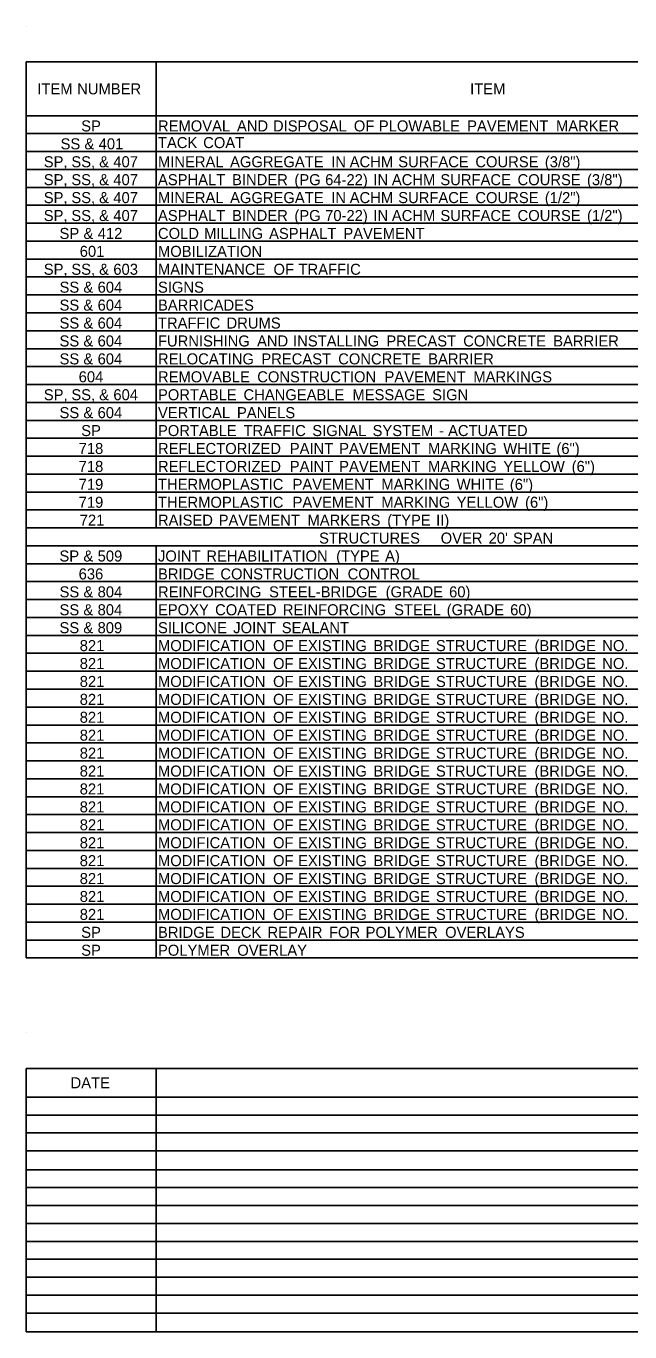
# Model space of a CAD drawing. Extents: x 544420 to 1930787, y -1947044 to 596640.
# Drawn here: x 552193 to 552521, y -1946914 to -1946204 of the extents above; entities that cross this region are included whole.
import ezdxf

# ---------------------------------------------------------------- set-up
doc = ezdxf.new("R2010")
doc.units = 0
doc.layers.add('Default', color=7, linetype='Continuous')

msp = doc.modelspace()

# ---------------------------------------------------------------- linework, layer by layer
at = {"layer": 'Default'}
for p, q in [((552192.61, -1946203.74), (552192.61, -1946203.74)), ((552192.61, -1946223.24), (552943.36, -1946223.24)), ((552192.61, -1946710.74), (552192.61, -1946223.24)), ((552263.3, -1946476.74), (552263.3, -1946223.24)), ((552192.61, -1946252.49), (552943.36, -1946252.49)), ((552192.61, -1946252.49), (552943.36, -1946252.49)), ((552263.3, -1946476.74), (552263.3, -1946252.49)), ((552192.61, -1946262.24), (552943.36, -1946262.24)), ((552192.61, -1946271.99), (552943.36, -1946271.99)), ((552192.61, -1946281.74), (552943.36, -1946281.74)), ((552192.61, -1946291.49), (552943.36, -1946291.49)), ((552192.61, -1946301.24), (552943.36, -1946301.24)), ((552192.61, -1946310.99), (552943.36, -1946310.99)), ((552192.61, -1946320.74), (552943.36, -1946320.74)), ((552192.61, -1946330.49), (552943.36, -1946330.49)), ((552192.61, -1946340.24), (552943.36, -1946340.24)), ((552192.61, -1946349.99), (552943.36, -1946349.99)), ((552192.61, -1946359.74), (552943.36, -1946359.74)), ((552192.61, -1946369.49), (552943.36, -1946369.49)), ((552192.61, -1946379.24), (552943.36, -1946379.24)), ((552192.61, -1946388.99), (552943.36, -1946388.99)), ((552192.61, -1946398.74), (552943.36, -1946398.74)), ((552192.61, -1946408.49), (552943.36, -1946408.49)), ((552192.61, -1946418.24), (552943.36, -1946418.24)), ((552192.61, -1946427.99), (552943.36, -1946427.99)), ((552192.61, -1946437.74), (552943.36, -1946437.74)), ((552192.61, -1946447.49), (552943.36, -1946447.49)), ((552192.61, -1946457.24), (552943.36, -1946457.24)), ((552192.61, -1946466.99), (552943.36, -1946466.99)), ((552192.61, -1946476.74), (552943.36, -1946476.74)), ((552192.61, -1946476.74), (552943.36, -1946476.74)), ((552192.61, -1946486.49), (552943.36, -1946486.49)), ((552192.61, -1946486.49), (552943.36, -1946486.49)), ((552263.3, -1946710.74), (552263.3, -1946486.49)), ((552263.3, -1946710.74), (552263.3, -1946486.49)), ((552192.61, -1946496.24), (552943.36, -1946496.24)), ((552192.61, -1946505.99), (552943.36, -1946505.99)), ((552192.61, -1946515.74), (552943.36, -1946515.74)), ((552192.61, -1946525.49), (552943.36, -1946525.49)), ((552192.61, -1946535.24), (552943.36, -1946535.24)), ((552192.61, -1946544.99), (552943.36, -1946544.99)), ((552263.3, -1946544.99), (552943.36, -1946544.99)), ((552192.61, -1946554.74), (552943.36, -1946554.74)), ((552263.3, -1946554.74), (552943.36, -1946554.74)), ((552192.61, -1946564.49), (552943.36, -1946564.49)), ((552263.3, -1946564.49), (552943.36, -1946564.49)), ((552192.61, -1946574.24), (552943.36, -1946574.24)), ((552263.3, -1946574.24), (552943.36, -1946574.24)), ((552192.61, -1946583.99), (552943.36, -1946583.99)), ((552263.3, -1946583.99), (552943.36, -1946583.99)), ((552192.61, -1946593.74), (552943.36, -1946593.74)), ((552263.3, -1946593.74), (552943.36, -1946593.74)), ((552192.61, -1946603.49), (552943.36, -1946603.49)), ((552263.3, -1946603.49), (552943.36, -1946603.49)), ((552192.61, -1946613.24), (552943.36, -1946613.24)), ((552263.3, -1946613.24), (552943.36, -1946613.24)), ((552192.61, -1946622.99), (552943.36, -1946622.99)), ((552263.3, -1946622.99), (552943.36, -1946622.99)), ((552192.61, -1946632.74), (552943.36, -1946632.74)), ((552263.3, -1946632.74), (552943.36, -1946632.74)), ((552192.61, -1946642.49), (552943.36, -1946642.49)), ((552263.3, -1946642.49), (552943.36, -1946642.49)), ((552192.61, -1946652.24), (552943.36, -1946652.24)), ((552263.3, -1946652.24), (552943.36, -1946652.24)), ((552192.61, -1946661.99), (552943.36, -1946661.99)), ((552263.3, -1946661.99), (552943.36, -1946661.99)), ((552192.61, -1946671.74), (552943.36, -1946671.74)), ((552263.3, -1946671.74), (552943.36, -1946671.74)), ((552192.61, -1946681.49), (552943.36, -1946681.49)), ((552263.3, -1946681.49), (552943.36, -1946681.49)), ((552192.61, -1946691.24), (552943.36, -1946691.24)), ((552263.3, -1946691.24), (552943.36, -1946691.24)), ((552192.61, -1946700.99), (552263.3, -1946700.99)), ((552192.61, -1946700.99), (552943.36, -1946700.99)), ((552192.61, -1946710.74), (552943.36, -1946710.74)), ((552192.61, -1946751.36), (552192.61, -1946751.36)), ((552192.61, -1946770.86), (552943.36, -1946770.86)), ((552192.61, -1946914.18), (552192.61, -1946770.86)), ((552263.3, -1946914.18), (552263.3, -1946770.86)), ((552192.61, -1946786.46), (552943.36, -1946786.46)), ((552192.61, -1946796.21), (552943.36, -1946796.21)), ((552192.61, -1946805.96), (552943.36, -1946805.96)), ((552192.61, -1946815.71), (552943.36, -1946815.71)), ((552192.61, -1946825.95), (552943.36, -1946825.95)), ((552192.61, -1946835.7), (552943.36, -1946835.7)), ((552192.61, -1946845.45), (552943.36, -1946845.45)), ((552192.61, -1946855.2), (552943.36, -1946855.2)), ((552192.61, -1946864.95), (552943.36, -1946864.95)), ((552192.61, -1946874.7), (552943.36, -1946874.7)), ((552192.61, -1946884.45), (552943.36, -1946884.45)), ((552192.61, -1946894.2), (552943.36, -1946894.2)), ((552192.61, -1946903.95), (552943.36, -1946903.95)), ((552192.61, -1946914.18), (552943.36, -1946914.18))]:
    msp.add_line(p, q, dxfattribs=at)

# ---------------------------------------------------------------- texts
for s, p in [('ITEM', (552198.7, -1946240.87)), (' NUMBER', (552218.12, -1946240.87)), ('ITEM', (552433.96, -1946240.87)), ('SP', (552222.54, -1946261.04)), ('REMOVAL', (552264.27, -1946261.04)), (' AND', (552304.97, -1946261.04)), (' DISPOSAL', (552324.55, -1946261.04)), (' OF', (552368.52, -1946261.04)), (' PLOWABLE', (552382.11, -1946261.04)), (' PAVEMENT', (552430.11, -1946261.04)), (' MARKER', (552478.4, -1946261.04)), ('SS', (552211.33, -1946270.79)), (' &', (552222.08, -1946270.79)), (' 401', (552229.81, -1946270.79)), ('TACK', (552264.27, -1946270.12)), (' COAT', (552286.62, -1946270.12)), ('SP,', (552202.19, -1946280.54)), (' SS,', (552214.96, -1946280.54)), (' &', (552230.06, -1946280.54)), (' 407', (552237.78, -1946280.54)), ('MINERAL', (552264.27, -1946280.54)), (' AGGREGATE', (552301.24, -1946280.54)), (' IN', (552356.23, -1946280.54)), (' ACHM', (552366.26, -1946280.54)), (' SURFACE', (552392.64, -1946280.54)), (' COURSE', (552434.58, -1946280.54)), (' (3/8")', (552472.34, -1946280.54)), ('SP,', (552202.19, -1946290.29)), (' SS,', (552214.96, -1946290.29)), (' &', (552230.06, -1946290.29)), (' 407', (552237.78, -1946290.29)), ('ASPHALT', (552264.27, -1946290.29)), (' BINDER', (552302.31, -1946290.29)), (' (PG', (552336.2, -1946290.29)), (' 64-22)', (552352.91, -1946290.29)), (' IN', (552379.15, -1946290.29)), (' ACHM', (552389.18, -1946290.29)), (' SURFACE', (552415.56, -1946290.29)), (' COURSE', (552457.51, -1946290.29)), (' (3/8")', (552495.26, -1946290.29)), ('SP,', (552202.19, -1946300.04)), (' SS,', (552214.96, -1946300.04)), (' &', (552230.06, -1946300.04)), (' 407', (552237.78, -1946300.04)), ('MINERAL', (552264.27, -1946300.04)), (' AGGREGATE', (552301.24, -1946300.04)), (' IN', (552356.23, -1946300.04)), (' ACHM', (552366.26, -1946300.04)), (' SURFACE', (552392.64, -1946300.04)), (' COURSE', (552434.58, -1946300.04)), (' (1/2")', (552472.34, -1946300.04)), ('SP,', (552202.19, -1946309.79)), (' SS,', (552214.96, -1946309.79)), (' &', (552230.06, -1946309.79)), (' 407', (552237.78, -1946309.79)), ('ASPHALT', (552264.27, -1946309.79)), (' BINDER', (552302.31, -1946309.79)), (' (PG', (552336.2, -1946309.79)), (' 70-22)', (552352.91, -1946309.79)), (' IN', (552379.15, -1946309.79)), (' ACHM', (552389.18, -1946309.79)), (' SURFACE', (552415.56, -1946309.79)), (' COURSE', (552457.51, -1946309.79)), (' (1/2")', (552495.26, -1946309.79)), ('SP', (552210.75, -1946319.54)), (' &', (552221.57, -1946319.54)), (' 412', (552229.29, -1946319.54)), ('COLD', (552264.27, -1946319.54)), (' MILLING', (552287.11, -1946319.54)), (' ASPHALT', (552322.45, -1946319.54)), (' PAVEMENT', (552362.82, -1946319.54)), ('601', (552221.73, -1946329.29)), ('MOBILIZATION', (552264.27, -1946329.29)), ('SP,', (552202.19, -1946339.04)), (' SS,', (552214.96, -1946339.04)), (' &', (552230.06, -1946339.04)), (' 603', (552237.78, -1946339.04)), ('MAINTENANCE', (552264.27, -1946339.04)), (' OF', (552324.85, -1946339.04)), (' TRAFFIC', (552338.43, -1946339.04)), ('SS', (552210.76, -1946348.79)), (' &', (552221.51, -1946348.79)), (' 604', (552229.24, -1946348.79)), ('SIGNS', (552264.27, -1946348.79)), ('SS', (552210.76, -1946358.54)), (' &', (552221.51, -1946358.54)), (' 604', (552229.24, -1946358.54)), ('BARRICADES', (552264.27, -1946358.54)), ('SS', (552210.76, -1946368.29)), (' &', (552221.51, -1946368.29)), (' 604', (552229.24, -1946368.29)), ('TRAFFIC', (552264.27, -1946368.29)), (' DRUMS', (552299.33, -1946368.29)), ('SS', (552210.76, -1946378.04)), (' &', (552221.51, -1946378.04)), (' 604', (552229.24, -1946378.04)), ('FURNISHING', (552264.27, -1946378.04)), (' AND', (552315.91, -1946378.04)), (' INSTALLING', (552335.49, -1946378.04)), (' PRECAST', (552386.21, -1946378.04)), (' CONCRETE', (552427.97, -1946378.04)), (' BARRIER', (552476.9, -1946378.04)), ('SS', (552210.76, -1946387.79)), (' &', (552221.51, -1946387.79)), (' 604', (552229.24, -1946387.79)), ('RELOCATING', (552264.27, -1946387.79)), (' PRECAST', (552318.25, -1946387.79)), (' CONCRETE', (552360.01, -1946387.79)), (' BARRIER', (552408.94, -1946387.79)), ('604', (552221.17, -1946397.54)), ('REMOVABLE', (552264.27, -1946397.54)), (' CONSTRUCTION', (552316.01, -1946397.54)), (' PAVEMENT', (552385.19, -1946397.54)), (' MARKINGS', (552433.47, -1946397.54)), ('SP,', (552202.21, -1946407.29)), (' SS,', (552214.97, -1946407.29)), (' &', (552230.07, -1946407.29)), (' 604', (552237.8, -1946407.29)), ('PORTABLE', (552264.27, -1946407.29)), (' CHANGEABLE', (552308.55, -1946407.29)), (' MESSAGE', (552367.74, -1946407.29)), (' SIGN', (552411.09, -1946407.29)), ('SS', (552210.76, -1946417.04)), (' &', (552221.51, -1946417.04)), (' 604', (552229.24, -1946417.04)), ('VERTICAL', (552264.27, -1946417.04)), (' PANELS', (552304.97, -1946417.04)), ('SP', (552222.54, -1946426.79)), ('PORTABLE', (552264.27, -1946426.79)), (' TRAFFIC', (552308.55, -1946426.79)), (' SIGNAL', (552345.94, -1946426.79)), (' SYSTEM', (552378.72, -1946426.79)), (' -', (552414.9, -1946426.79)), (' ACTUATED', (552419.75, -1946426.79)), ('718', (552221.15, -1946436.54)), ('REFLECTORIZED', (552264.27, -1946436.54)), (' PAINT', (552333.7, -1946436.54)), (' PAVEMENT', (552360.55, -1946436.54)), (' MARKING', (552408.83, -1946436.54)), (' WHITE', (552449.76, -1946436.54)), (' (6")', (552478.65, -1946436.54)), ('718', (552221.15, -1946446.29)), ('REFLECTORIZED', (552264.27, -1946446.29)), (' PAINT', (552333.7, -1946446.29)), (' PAVEMENT', (552360.55, -1946446.29)), (' MARKING', (552408.83, -1946446.29)), (' YELLOW', (552449.76, -1946446.29)), (' (6")', (552486.93, -1946446.29)), ('719', (552221.15, -1946456.04)), ('THERMOPLASTIC', (552264.27, -1946456.04)), (' PAVEMENT', (552335.21, -1946456.04)), (' MARKING', (552383.49, -1946456.04)), (' WHITE', (552424.42, -1946456.04)), (' (6")', (552453.31, -1946456.04)), ('719', (552221.15, -1946465.79)), ('THERMOPLASTIC', (552264.27, -1946465.79)), (' PAVEMENT', (552335.21, -1946465.79)), (' MARKING', (552383.49, -1946465.79)), (' YELLOW', (552424.42, -1946465.79)), (' (6")', (552461.59, -1946465.79)), ('721', (552221.73, -1946475.54)), ('RAISED', (552264.27, -1946475.54)), (' PAVEMENT', (552295.04, -1946475.54)), (' MARKERS', (552343.32, -1946475.54)), (' (TYPE', (552386.68, -1946475.54)), (' II)', (552413.25, -1946475.54)), ('                                                                       STRUCTURES', (552193.58, -1946485.29)), (' OVER', (552415.74, -1946485.29)), (" 20'", (552441.79, -1946485.29)), (' SPAN', (552455.06, -1946485.29)), ('SP', (552210.71, -1946495.04)), (' &', (552221.53, -1946495.04)), (' 509', (552229.26, -1946495.04)), ('JOINT', (552264.27, -1946495.04)), (' REHABILITATION', (552288.32, -1946495.04)), (' (TYPE', (552358.91, -1946495.04)), (' A)', (552385.48, -1946495.04)), ('636', (552221.15, -1946504.79)), ('BRIDGE', (552264.27, -1946504.79)), (' CONSTRUCTION', (552295.97, -1946504.79)), (' CONTROL', (552365.15, -1946504.79)), ('SS', (552210.76, -1946514.54)), (' &', (552221.51, -1946514.54)), (' 804', (552229.24, -1946514.54)), ('REINFORCING', (552264.27, -1946514.54)), (' STEEL-BRIDGE', (552322.43, -1946514.54)), (' (GRADE', (552385.81, -1946514.54)), (' 60)', (552420.29, -1946514.54)), (' (GRADE', (552419, -1946524.29)), (' 60)', (552453.49, -1946524.29)), ('SS', (552210.76, -1946524.29)), (' &', (552221.51, -1946524.29)), (' 804', (552229.24, -1946524.29)), ('EPOXY', (552264.27, -1946524.29)), (' COATED', (552293.1, -1946524.29)), (' REINFORCING', (552329.92, -1946524.29)), (' STEEL', (552390.41, -1946524.29)), ('SS', (552210.75, -1946534.04)), (' &', (552221.49, -1946534.04)), (' 809', (552229.22, -1946534.04)), ('SILICONE', (552264.27, -1946534.04)), (' JOINT', (552302.96, -1946534.04)), (' SEALANT', (552329.33, -1946534.04)), ('821', (552221.73, -1946543.79)), ('MODIFICATION', (552264.27, -1946543.79)), (' OF', (552324.6, -1946543.79)), (' EXISTING', (552338.18, -1946543.79)), (' BRIDGE', (552379.12, -1946543.79)), (' STRUCTURE', (552413.14, -1946543.79)), (' (BRIDGE', (552466.73, -1946543.79)), (' NO.', (552503.54, -1946543.79)), ('821', (552221.73, -1946553.54)), ('MODIFICATION', (552264.27, -1946553.54)), (' OF', (552324.6, -1946553.54)), (' EXISTING', (552338.18, -1946553.54)), (' BRIDGE', (552379.12, -1946553.54)), (' STRUCTURE', (552413.14, -1946553.54)), (' (BRIDGE', (552466.73, -1946553.54)), (' NO.', (552503.54, -1946553.54)), ('821', (552221.73, -1946563.29)), ('MODIFICATION', (552264.27, -1946563.29)), (' OF', (552324.6, -1946563.29)), (' EXISTING', (552338.18, -1946563.29)), (' BRIDGE', (552379.12, -1946563.29)), (' STRUCTURE', (552413.14, -1946563.29)), (' (BRIDGE', (552466.73, -1946563.29)), (' NO.', (552503.54, -1946563.29)), ('821', (552221.73, -1946573.04)), ('MODIFICATION', (552264.27, -1946573.04)), (' OF', (552324.6, -1946573.04)), (' EXISTING', (552338.18, -1946573.04)), (' BRIDGE', (552379.12, -1946573.04)), (' STRUCTURE', (552413.14, -1946573.04)), (' (BRIDGE', (552466.73, -1946573.04)), (' NO.', (552503.54, -1946573.04)), ('821', (552221.73, -1946582.79)), ('MODIFICATION', (552264.27, -1946582.79)), (' OF', (552324.6, -1946582.79)), (' EXISTING', (552338.18, -1946582.79)), (' BRIDGE', (552379.12, -1946582.79)), (' STRUCTURE', (552413.14, -1946582.79)), (' (BRIDGE', (552466.73, -1946582.79)), (' NO.', (552503.54, -1946582.79)), ('821', (552221.73, -1946592.54)), ('MODIFICATION', (552264.27, -1946592.54)), (' OF', (552324.6, -1946592.54)), (' EXISTING', (552338.18, -1946592.54)), (' BRIDGE', (552379.12, -1946592.54)), (' STRUCTURE', (552413.14, -1946592.54)), (' (BRIDGE', (552466.73, -1946592.54)), (' NO.', (552503.54, -1946592.54)), ('821', (552221.73, -1946602.29)), ('MODIFICATION', (552264.27, -1946602.29)), (' OF', (552324.6, -1946602.29)), (' EXISTING', (552338.18, -1946602.29)), (' BRIDGE', (552379.12, -1946602.29)), (' STRUCTURE', (552413.14, -1946602.29)), (' (BRIDGE', (552466.73, -1946602.29)), (' NO.', (552503.54, -1946602.29)), ('821', (552221.73, -1946612.04)), ('MODIFICATION', (552264.27, -1946612.04)), (' OF', (552324.6, -1946612.04)), (' EXISTING', (552338.18, -1946612.04)), (' BRIDGE', (552379.12, -1946612.04)), (' STRUCTURE', (552413.14, -1946612.04)), (' (BRIDGE', (552466.73, -1946612.04)), (' NO.', (552503.54, -1946612.04)), ('821', (552221.73, -1946621.79)), ('MODIFICATION', (552264.27, -1946621.79)), (' OF', (552324.6, -1946621.79)), (' EXISTING', (552338.18, -1946621.79)), (' BRIDGE', (552379.12, -1946621.79)), (' STRUCTURE', (552413.14, -1946621.79)), (' (BRIDGE', (552466.73, -1946621.79)), (' NO.', (552503.54, -1946621.79)), ('821', (552221.73, -1946631.54)), ('MODIFICATION', (552264.27, -1946631.54)), (' OF', (552324.6, -1946631.54)), (' EXISTING', (552338.18, -1946631.54)), (' BRIDGE', (552379.12, -1946631.54)), (' STRUCTURE', (552413.14, -1946631.54)), (' (BRIDGE', (552466.73, -1946631.54)), (' NO.', (552503.54, -1946631.54)), ('821', (552221.73, -1946641.29)), ('MODIFICATION', (552264.27, -1946641.29)), (' OF', (552324.6, -1946641.29)), (' EXISTING', (552338.18, -1946641.29)), (' BRIDGE', (552379.12, -1946641.29)), (' STRUCTURE', (552413.14, -1946641.29)), (' (BRIDGE', (552466.73, -1946641.29)), (' NO.', (552503.54, -1946641.29)), ('821', (552221.73, -1946651.04)), ('MODIFICATION', (552264.27, -1946651.04)), (' OF', (552324.6, -1946651.04)), (' EXISTING', (552338.18, -1946651.04)), (' BRIDGE', (552379.12, -1946651.04)), (' STRUCTURE', (552413.14, -1946651.04)), (' (BRIDGE', (552466.73, -1946651.04)), (' NO.', (552503.54, -1946651.04)), ('821', (552221.73, -1946660.79)), ('MODIFICATION', (552264.27, -1946660.79)), (' OF', (552324.6, -1946660.79)), (' EXISTING', (552338.18, -1946660.79)), (' BRIDGE', (552379.12, -1946660.79)), (' STRUCTURE', (552413.14, -1946660.79)), (' (BRIDGE', (552466.73, -1946660.79)), (' NO.', (552503.54, -1946660.79)), ('821', (552221.73, -1946670.54)), ('MODIFICATION', (552264.27, -1946670.54)), (' OF', (552324.6, -1946670.54)), (' EXISTING', (552338.18, -1946670.54)), (' BRIDGE', (552379.12, -1946670.54)), (' STRUCTURE', (552413.14, -1946670.54)), (' (BRIDGE', (552466.73, -1946670.54)), (' NO.', (552503.54, -1946670.54)), ('821', (552221.73, -1946680.29)), ('MODIFICATION', (552264.27, -1946680.29)), (' OF', (552324.6, -1946680.29)), (' EXISTING', (552338.18, -1946680.29)), (' BRIDGE', (552379.12, -1946680.29)), (' STRUCTURE', (552413.14, -1946680.29)), (' (BRIDGE', (552466.73, -1946680.29)), (' NO.', (552503.54, -1946680.29)), ('821', (552221.73, -1946690.04)), ('MODIFICATION', (552264.27, -1946690.04)), (' OF', (552324.6, -1946690.04)), (' EXISTING', (552338.18, -1946690.04)), (' BRIDGE', (552379.12, -1946690.04)), (' STRUCTURE', (552413.14, -1946690.04)), (' (BRIDGE', (552466.73, -1946690.04)), (' NO.', (552503.54, -1946690.04)), ('SP', (552222.54, -1946699.79)), ('BRIDGE', (552264.27, -1946699.79)), (' DECK', (552295.97, -1946699.79)), (' REPAIR', (552321.57, -1946699.79)), (' FOR', (552355, -1946699.79)), (' POLYMER', (552374.91, -1946699.79)), (' OVERLAYS', (552418.13, -1946699.79)), ('SP', (552222.54, -1946709.54)), ('POLYMER', (552264.27, -1946709.54)), (' OVERLAY', (552305.16, -1946709.54)), ('DATE', (552216.75, -1946781.66))]:
    msp.add_text(s, height=6, dxfattribs=at).set_placement(p)

doc.saveas('drawing.dxf')
